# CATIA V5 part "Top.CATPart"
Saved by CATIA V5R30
Part number: Part1.1
Bounding box of the stored display mesh (mm): x -50 to 50, y -25 to 25, z -20 to 0
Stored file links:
  D:\PROJECTS\CATIA V56R 2020\Resources\Parts File\c12_catia_v5_6r2020_prt\c12_catia_v5-6r2020 figr_12-8\Top.CATPart
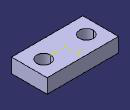
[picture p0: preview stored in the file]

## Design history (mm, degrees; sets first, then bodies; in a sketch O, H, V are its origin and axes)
Body1 (main body)
  Sketch1 on xy-plane, origin (0, 0, 0), H (1, 0, 0), V (0, 1, 0)
    line L1 (50, 25) -> (50, -25)
    line L2 (50, -25) -> (-50, -25)
    line L3 (-50, -25) -> (-50, 25)
    line L4 (-50, 25) -> (50, 25)
    circle A1 centre (-30, 0) radius 10
    point P5 (-30, 0)
    circle A2 centre (30, 0) radius 10
    length L2 = 100
    length L1 = 50
    radius A1 = 10
    distance P5 V = 30
    vertical: L1 V, L3 V
    horizontal: L2 H, L4 H
    equidistance: L1 L3 O, L2 L4 O
    coincidence: P5 H
    symmetry: A1 A2 V
  Pad1: profile Sketch1, direction (0, 0, -1), length 20
  Sketch2 on face of Pad1, origin (0, 0, 0), H (1, 0, 0), V (0, 1, 0)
